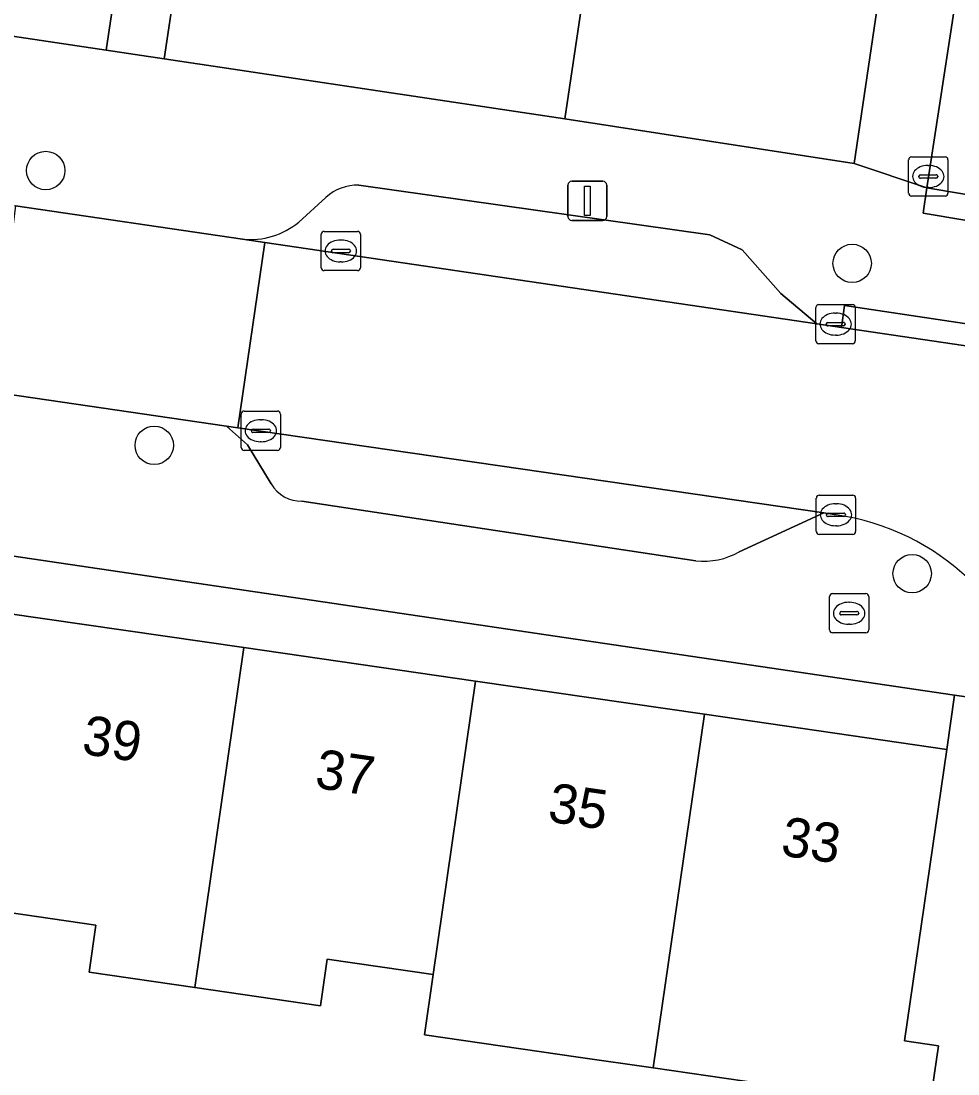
# Model space of a CAD drawing. Extents: x 163683 to 164494, y 382709 to 383872.
# Drawn here: x 164016.58 to 164040.44, y 383034.95 to 383061.77 of the extents above; entities that cross this region are included whole.
import ezdxf

# ---------------------------------------------------------------- set-up
doc = ezdxf.new("R2010")
doc.units = 0
for name, color, linetype in [('IMGEO_Boom', 7, 'Continuous'), ('IMGEO_Brandkraan', 7, 'Continuous'), ('IMGEO_Erf', 7, 'Continuous'), ('IMGEO_Kolk', 7, 'Continuous'), ('IMGEO_Lichtmast', 7, 'Continuous'), ('IMGEO_Pand', 7, 'Continuous'), ('IMGEO_Pand_nummerreeks', 7, 'Continuous'), ('IMGEO_Parkeervlak_open', 7, 'Continuous'), ('IMGEO_Rijbaan_lokaal_open', 7, 'Continuous'), ('IMGEO_Voetpad_open', 7, 'Continuous')]:
    doc.layers.add(name, color=color, linetype=linetype)

msp = doc.modelspace()

# ---------------------------------------------------------------- linework, layer by layer
at = {"layer": 'IMGEO_Boom'}
for centre in [(164017.204, 383057.959), (164037.749, 383055.594), (164019.968, 383050.961), (164039.278, 383047.694)]:
    msp.add_circle(centre, 0.489, dxfattribs=at)
at = {"layer": 'IMGEO_Brandkraan'}
for p, q in [((164037.172, 383046.259), (164037.172, 383047.111)), ((164037.247, 383047.185), (164038.099, 383047.185)), ((164038.173, 383047.111), (164038.173, 383046.259)), ((164037.474, 383046.728), (164037.872, 383046.728)), ((164037.66, 383046.965), (164037.685, 383046.965)), ((164037.431, 383046.679), (164037.431, 383046.691)), ((164037.869, 383046.642), (164037.471, 383046.642)), ((164037.915, 383046.691), (164037.915, 383046.679)), ((164037.683, 383046.405), (164037.658, 383046.405)), ((164038.099, 383046.185), (164037.247, 383046.185))]:
    msp.add_line(p, q, dxfattribs=at)
for points in [[(164037.172, 383046.259), (164037.172, 383047.111)], [(164037.247, 383047.185), (164038.099, 383047.185)], [(164038.173, 383047.111), (164038.173, 383046.259)], [(164038.099, 383046.185), (164037.247, 383046.185)]]:
    msp.add_lwpolyline(points, dxfattribs=at)
for centre, radius, start, end in [((164037.249, 383047.109), 0.0765, 91.552, 178.448), ((164037.249, 383047.109), 0.0765, 91.552, 178.448), ((164038.097, 383047.109), 0.0765, 1.552, 88.448), ((164038.097, 383047.109), 0.0765, 1.552, 88.448), ((164037.471, 383046.688), 0.0403, 85.8775, 175.7526), ((164037.876, 383046.69), 0.0386, 1.7309, 96.639), ((164037.468, 383046.678), 0.0366, 178.938, 274.7102), ((164037.872, 383046.685), 0.043, 264.8664, 352.4533), ((164037.249, 383046.261), 0.0765, 181.552, 268.448), ((164037.249, 383046.261), 0.0765, 181.552, 268.448), ((164038.097, 383046.261), 0.0765, 271.552, 358.448), ((164038.097, 383046.261), 0.0765, 271.552, 358.448)]:
    msp.add_arc(centre, radius, start, end, dxfattribs=at)
for centre, major_axis, ratio, start_param, end_param in [((164037.659, 383046.685), (-0.387, 0.002), 0.722429, 4.712389, 7.853982), ((164037.684, 383046.685), (-0.39, 0.002), 0.717154, 1.570796, 4.712389)]:
    msp.add_ellipse(centre, major_axis=major_axis, ratio=ratio, start_param=start_param, end_param=end_param, dxfattribs=at)
at = {"layer": 'IMGEO_Erf'}
for points in [[(164022.964, 383089.182), (164012.951, 383090.682), (164012.41, 383087.025), (164018.347, 383086.148), (164017.834, 383082.676), (164017.616, 383081.202), (164017.328, 383079.253), (164011.392, 383080.13), (164010.87, 383076.601), (164010.353, 383073.107), (164016.29, 383072.23), (164016.005, 383070.301), (164015.775, 383068.743), (164015.274, 383065.354), (164009.338, 383066.231), (164008.789, 383062.521), (164018.747, 383061.027)], [(164033.045, 383076.853), (164027.111, 383077.737), (164027.209, 383078.398), (164027.643, 383081.312), (164024.777, 383081.738), (164025.045, 383083.549), (164027.913, 383083.122), (164028.136, 383084.621), (164034.07, 383083.737), (164034.621, 383087.436), (164024.449, 383088.96), (164020.223, 383060.805), (164030.426, 383059.273), (164030.971, 383062.937), (164025.038, 383063.821), (164025.558, 383067.31), (164025.775, 383068.767), (164026.062, 383070.695), (164031.996, 383069.811), (164032.527, 383073.373)], [(163992.865, 383051.505), (163992.635, 383050.168), (163998.612, 383049.251), (164000, 383049.038), (164004.619, 383048.366), (164010.494, 383047.515), (164016.184, 383046.691), (164022.254, 383045.812), (164028.157, 383044.958), (164033.985, 383044.114), (164040.159, 383043.219), (164040.359, 383044.602), (164000.002, 383050.556), (163995.18, 383051.197)]]:
    msp.add_lwpolyline(points, close=True, dxfattribs=at)
msp.add_lwpolyline([(164035.482, 383034.702), (164032.681, 383035.108), (164030.771, 383035.384), (164026.853, 383035.951), (164027.075, 383037.486), (164024.374, 383037.877), (164024.202, 383036.692), (164021.001, 383037.156), (164018.311, 383037.546), (164018.484, 383038.741), (164015.104, 383039.231)], dxfattribs=at)
at = {"layer": 'IMGEO_Kolk'}
for p, q in [((164039.263, 383058.308), (164040.115, 383058.308)), ((164039.188, 383057.382), (164039.188, 383058.234)), ((164039.676, 383058.088), (164039.701, 383058.088)), ((164040.189, 383058.234), (164040.189, 383057.382)), ((164039.447, 383057.802), (164039.447, 383057.814)), ((164039.885, 383057.765), (164039.487, 383057.765)), ((164039.49, 383057.851), (164039.888, 383057.851)), ((164039.931, 383057.814), (164039.931, 383057.802)), ((164039.699, 383057.528), (164039.674, 383057.528)), ((164040.115, 383057.308), (164039.263, 383057.308)), ((164024.297, 383056.41), (164025.149, 383056.41)), ((164024.222, 383055.484), (164024.222, 383056.336)), ((164024.71, 383056.19), (164024.735, 383056.19)), ((164025.223, 383056.336), (164025.223, 383055.484)), ((164024.481, 383055.904), (164024.481, 383055.916)), ((164024.919, 383055.867), (164024.521, 383055.867)), ((164024.524, 383055.953), (164024.922, 383055.953)), ((164024.965, 383055.916), (164024.965, 383055.904)), ((164024.733, 383055.63), (164024.708, 383055.63)), ((164025.149, 383055.41), (164024.297, 383055.41)), ((164036.902, 383054.548), (164037.754, 383054.548)), ((164036.827, 383053.622), (164036.827, 383054.474)), ((164037.315, 383054.328), (164037.34, 383054.328)), ((164037.828, 383054.474), (164037.828, 383053.622)), ((164037.086, 383054.042), (164037.086, 383054.054)), ((164037.524, 383054.005), (164037.126, 383054.005)), ((164037.129, 383054.091), (164037.527, 383054.091)), ((164037.57, 383054.054), (164037.57, 383054.042)), ((164037.338, 383053.768), (164037.313, 383053.768)), ((164037.754, 383053.548), (164036.902, 383053.548)), ((164022.26, 383051.833), (164023.112, 383051.833)), ((164022.185, 383050.907), (164022.185, 383051.759)), ((164022.673, 383051.613), (164022.698, 383051.613)), ((164023.186, 383051.759), (164023.186, 383050.907)), ((164022.444, 383051.327), (164022.444, 383051.339)), ((164022.882, 383051.29), (164022.484, 383051.29)), ((164022.487, 383051.376), (164022.885, 383051.376)), ((164022.928, 383051.339), (164022.928, 383051.327)), ((164022.696, 383051.053), (164022.671, 383051.053)), ((164023.112, 383050.833), (164022.26, 383050.833)), ((164036.911, 383049.693), (164037.763, 383049.693)), ((164036.836, 383048.767), (164036.836, 383049.619)), ((164037.324, 383049.473), (164037.349, 383049.473)), ((164037.837, 383049.619), (164037.837, 383048.767)), ((164037.095, 383049.187), (164037.095, 383049.199)), ((164037.533, 383049.15), (164037.135, 383049.15)), ((164037.138, 383049.236), (164037.536, 383049.236)), ((164037.579, 383049.199), (164037.579, 383049.187)), ((164037.347, 383048.913), (164037.322, 383048.913)), ((164037.763, 383048.693), (164036.911, 383048.693))]:
    msp.add_line(p, q, dxfattribs=at)
for points in [[(164039.263, 383058.308), (164040.115, 383058.308)], [(164039.188, 383057.382), (164039.188, 383058.234)], [(164040.189, 383058.234), (164040.189, 383057.382)], [(164040.115, 383057.308), (164039.263, 383057.308)], [(164024.297, 383056.41), (164025.149, 383056.41)], [(164024.222, 383055.484), (164024.222, 383056.336)], [(164025.223, 383056.336), (164025.223, 383055.484)], [(164025.149, 383055.41), (164024.297, 383055.41)], [(164036.902, 383054.548), (164037.754, 383054.548)], [(164036.827, 383053.622), (164036.827, 383054.474)], [(164037.828, 383054.474), (164037.828, 383053.622)], [(164037.754, 383053.548), (164036.902, 383053.548)], [(164022.26, 383051.833), (164023.112, 383051.833)], [(164022.185, 383050.907), (164022.185, 383051.759)], [(164023.186, 383051.759), (164023.186, 383050.907)], [(164023.112, 383050.833), (164022.26, 383050.833)], [(164036.911, 383049.693), (164037.763, 383049.693)], [(164036.836, 383048.767), (164036.836, 383049.619)], [(164037.837, 383049.619), (164037.837, 383048.767)], [(164037.763, 383048.693), (164036.911, 383048.693)]]:
    msp.add_lwpolyline(points, dxfattribs=at)
for centre, radius, start, end in [((164039.265, 383058.232), 0.0765, 91.552, 178.448), ((164039.265, 383058.232), 0.0765, 91.552, 178.448), ((164040.113, 383058.232), 0.0765, 1.552, 88.448), ((164040.113, 383058.232), 0.0765, 1.552, 88.448), ((164039.487, 383057.811), 0.0403, 85.8775, 175.7526), ((164039.484, 383057.801), 0.0366, 178.938, 274.7102), ((164039.888, 383057.808), 0.043, 264.8664, 352.4533), ((164039.892, 383057.813), 0.0386, 1.7309, 96.639), ((164039.265, 383057.384), 0.0765, 181.552, 268.448), ((164039.265, 383057.384), 0.0765, 181.552, 268.448), ((164040.113, 383057.384), 0.0765, 271.552, 358.448), ((164040.113, 383057.384), 0.0765, 271.552, 358.448), ((164024.299, 383056.334), 0.0765, 91.552, 178.448), ((164024.299, 383056.334), 0.0765, 91.552, 178.448), ((164025.147, 383056.334), 0.0765, 1.552, 88.448), ((164025.147, 383056.334), 0.0765, 1.552, 88.448), ((164024.521, 383055.913), 0.0403, 85.8775, 175.7526), ((164024.518, 383055.903), 0.0366, 178.938, 274.7102), ((164024.922, 383055.91), 0.043, 264.8664, 352.4533), ((164024.926, 383055.915), 0.0386, 1.7309, 96.639), ((164024.299, 383055.486), 0.0765, 181.552, 268.448), ((164024.299, 383055.486), 0.0765, 181.552, 268.448), ((164025.147, 383055.486), 0.0765, 271.552, 358.448), ((164025.147, 383055.486), 0.0765, 271.552, 358.448), ((164036.904, 383054.472), 0.0765, 91.552, 178.448), ((164036.904, 383054.472), 0.0765, 91.552, 178.448), ((164037.752, 383054.472), 0.0765, 1.552, 88.448), ((164037.752, 383054.472), 0.0765, 1.552, 88.448), ((164037.126, 383054.051), 0.0403, 85.8775, 175.7526), ((164037.123, 383054.041), 0.0366, 178.938, 274.7102), ((164037.527, 383054.048), 0.043, 264.8664, 352.4533), ((164037.531, 383054.053), 0.0386, 1.7309, 96.639), ((164036.904, 383053.624), 0.0765, 181.552, 268.448), ((164036.904, 383053.624), 0.0765, 181.552, 268.448), ((164037.752, 383053.624), 0.0765, 271.552, 358.448), ((164037.752, 383053.624), 0.0765, 271.552, 358.448), ((164022.262, 383051.757), 0.0765, 91.552, 178.448), ((164022.262, 383051.757), 0.0765, 91.552, 178.448), ((164023.11, 383051.757), 0.0765, 1.552, 88.448), ((164023.11, 383051.757), 0.0765, 1.552, 88.448), ((164022.484, 383051.336), 0.0403, 85.8775, 175.7526), ((164022.481, 383051.326), 0.0366, 178.938, 274.7102), ((164022.885, 383051.333), 0.043, 264.8664, 352.4533), ((164022.889, 383051.338), 0.0386, 1.7309, 96.639), ((164022.262, 383050.909), 0.0765, 181.552, 268.448), ((164022.262, 383050.909), 0.0765, 181.552, 268.448), ((164023.11, 383050.909), 0.0765, 271.552, 358.448), ((164023.11, 383050.909), 0.0765, 271.552, 358.448), ((164036.913, 383049.617), 0.0765, 91.552, 178.448), ((164036.913, 383049.617), 0.0765, 91.552, 178.448), ((164037.761, 383049.617), 0.0765, 1.552, 88.448), ((164037.761, 383049.617), 0.0765, 1.552, 88.448), ((164037.135, 383049.196), 0.0403, 85.8775, 175.7526), ((164037.132, 383049.186), 0.0366, 178.938, 274.7102), ((164037.536, 383049.193), 0.043, 264.8664, 352.4533), ((164037.54, 383049.198), 0.0386, 1.7309, 96.639), ((164036.913, 383048.769), 0.0765, 181.552, 268.448), ((164036.913, 383048.769), 0.0765, 181.552, 268.448), ((164037.761, 383048.769), 0.0765, 271.552, 358.448), ((164037.761, 383048.769), 0.0765, 271.552, 358.448)]:
    msp.add_arc(centre, radius, start, end, dxfattribs=at)
for centre, major_axis, ratio, start_param, end_param in [((164039.675, 383057.808), (-0.387, 0.002), 0.722429, 4.712389, 7.853982), ((164039.7, 383057.808), (-0.39, 0.002), 0.717154, 1.570796, 4.712389), ((164024.709, 383055.91), (-0.387, 0.002), 0.722429, 4.712389, 7.853982), ((164024.734, 383055.91), (-0.39, 0.002), 0.717154, 1.570796, 4.712389), ((164037.314, 383054.048), (-0.387, 0.002), 0.722429, 4.712389, 7.853982), ((164037.339, 383054.048), (-0.39, 0.002), 0.717154, 1.570796, 4.712389), ((164022.672, 383051.333), (-0.387, 0.002), 0.722429, 4.712389, 7.853982), ((164022.697, 383051.333), (-0.39, 0.002), 0.717154, 1.570796, 4.712389), ((164037.323, 383049.193), (-0.387, 0.002), 0.722429, 4.712389, 7.853982), ((164037.348, 383049.193), (-0.39, 0.002), 0.717154, 1.570796, 4.712389)]:
    msp.add_ellipse(centre, major_axis=major_axis, ratio=ratio, start_param=start_param, end_param=end_param, dxfattribs=at)
at = {"layer": 'IMGEO_Lichtmast'}
for p, q in [((164030.508, 383056.787), (164030.508, 383057.587)), ((164030.508, 383057.587), (164030.508, 383056.787)), ((164030.608, 383057.687), (164031.398, 383057.687)), ((164031.398, 383057.687), (164030.608, 383057.687)), ((164031.498, 383057.587), (164031.498, 383056.787)), ((164031.498, 383056.787), (164031.498, 383057.587)), ((164031.398, 383056.687), (164030.608, 383056.687)), ((164030.608, 383056.687), (164031.398, 383056.687))]:
    msp.add_line(p, q, dxfattribs=at)
msp.add_lwpolyline([(164030.928, 383057.562), (164031.078, 383057.562), (164031.078, 383056.812), (164030.928, 383056.812), (164030.928, 383057.562)], dxfattribs=at)
for centre, start, end in [((164030.608, 383057.587), 90, 180), ((164030.608, 383057.587), 90, 180), ((164031.398, 383057.587), 0, 90), ((164031.398, 383057.587), 360, 90), ((164030.608, 383056.787), 180, 270), ((164030.608, 383056.787), 180, 270), ((164031.398, 383056.787), 270, 0), ((164031.398, 383056.787), 270, 0)]:
    msp.add_arc(centre, 0.1, start, end, dxfattribs=at)
at = {"layer": 'IMGEO_Pand'}
for points in [[(164025.558, 383067.31), (164025.038, 383063.821), (164030.971, 383062.937), (164030.426, 383059.273), (164037.802, 383058.142), (164038.851, 383065.265)], [(164016.184, 383046.691), (164015.104, 383039.231), (164018.484, 383038.741), (164018.311, 383037.546), (164021.001, 383037.156), (164022.254, 383045.812)], [(164028.157, 383044.958), (164022.254, 383045.812), (164021.001, 383037.156), (164024.202, 383036.692), (164024.374, 383037.877), (164027.075, 383037.486)], [(164028.157, 383044.958), (164027.075, 383037.486), (164026.853, 383035.951), (164030.771, 383035.384), (164032.681, 383035.108), (164033.985, 383044.114)], [(164033.985, 383044.114), (164032.681, 383035.108), (164035.482, 383034.702), (164035.417, 383034.26), (164039.652, 383033.645), (164039.946, 383035.673), (164039.085, 383035.797), (164040.159, 383043.219)]]:
    msp.add_lwpolyline(points, close=True, dxfattribs=at)
at = {"layer": 'IMGEO_Parkeervlak_open'}
for points in [[(164034.127, 383056.318), (164025.178, 383057.585)], [(164024.342, 383057.275), (164023.656, 383056.646)], [(164022.215, 383056.211), (164022.788, 383056.127), (164036.851, 383054.058), (164035.934, 383054.824), (164034.947, 383055.94), (164034.127, 383056.318)], [(164034.871, 383048.252), (164037.025, 383049.239), (164022.095, 383051.409), (164021.809, 383051.451), (164022.349, 383050.977), (164022.951, 383049.98)], [(164023.732, 383049.542), (164033.767, 383048.021)]]:
    msp.add_lwpolyline(points, dxfattribs=at)
for centre, radius, start, end in [((164025.134, 383056.421), 1.165, 87.8374, 132.8535), ((164022.405, 383058.186), 1.984, 264.5086, 309.0867), ((164023.7, 383050.4), 0.858, 209.2735, 272.1574), ((164033.968, 383049.812), 1.802, 263.5815, 300.0546)]:
    msp.add_arc(centre, radius, start, end, dxfattribs=at)
at = {"layer": 'IMGEO_Rijbaan_lokaal_open'}
for points in [[(164043.851, 383085.289), (164043.854, 383085.06), (164043.271, 383081.092), (164039.653, 383057.519), (164042.978, 383056.96), (164045.921, 383076.806), (164045.976, 383077.163), (164046.054, 383077.691)], [(164053.938, 383046.726), (164055.214, 383046.537), (164072.333, 383043.999), (164073.069, 383048.725), (164056.229, 383051.203), (164055.32, 383051.337), (164048.406, 383052.355), (164044.209, 383052.972), (164037.476, 383053.965), (164036.851, 383054.058), (164022.788, 383056.127), (164022.095, 383051.409), (164037.025, 383049.239), (164037.34, 383049.193)]]:
    msp.add_lwpolyline(points, dxfattribs=at)
for points in [[(164042.84, 383056.324), (164042.911, 383056.507), (164042.978, 383056.96), (164039.653, 383057.519), (164039.556, 383056.876)], [(164022.095, 383051.409), (164022.788, 383056.127), (164022.215, 383056.211), (164016.437, 383057.059), (164015.819, 383052.322), (164021.809, 383051.451)]]:
    msp.add_lwpolyline(points, close=True, dxfattribs=at)
msp.add_arc((164036.439, 383043.016), 6.242, 11.7018, 81.7045, dxfattribs=at)
at = {"layer": 'IMGEO_Voetpad_open'}
for points in [[(164024.449, 383088.96), (164022.964, 383089.182), (164018.747, 383061.027), (164020.223, 383060.805)], [(164043.271, 383081.092), (164043.854, 383085.06), (164043.851, 383085.289), (164043.843, 383085.984), (164041.955, 383086.344), (164040.913, 383079.27), (164039.878, 383072.242), (164038.851, 383065.265), (164037.802, 383058.142), (164039.653, 383057.519)], [(164044.209, 383052.972), (164044.29, 383053.516), (164037.557, 383054.519), (164037.476, 383053.965)]]:
    msp.add_lwpolyline(points, close=True, dxfattribs=at)
for points in [[(164056.633, 383055.356), (164054.596, 383055.242), (164054.5, 383054.599), (164051.188, 383055.135), (164042.84, 383056.324), (164039.556, 383056.876), (164039.653, 383057.519), (164037.802, 383058.142), (164030.426, 383059.273), (164020.223, 383060.805), (164018.747, 383061.027), (164008.789, 383062.521), (164001.464, 383063.621), (163999.41, 383063.224), (163999.316, 383062.59), (163995.848, 383063.119), (163990.75, 383063.896), (163988.526, 383062.149), (163985.466, 383059.738)], [(164004.603, 383060.549), (164014.034, 383059.188), (164015.06, 383058.752), (164016.315, 383057.077), (164016.437, 383057.059), (164022.215, 383056.211)], [(164025.178, 383057.585), (164034.127, 383056.318), (164034.947, 383055.94), (164035.934, 383054.824), (164036.851, 383054.058), (164037.476, 383053.965), (164037.557, 383054.519), (164044.29, 383053.516), (164044.209, 383052.972), (164048.406, 383052.355), (164048.485, 383052.884), (164055.396, 383051.842), (164055.32, 383051.337), (164056.229, 383051.203), (164057.386, 383051.395), (164058.376, 383052.117)], [(164023.656, 383056.646), (164024.342, 383057.275)], [(164022.951, 383049.98), (164022.349, 383050.977), (164021.809, 383051.451), (164015.819, 383052.322)], [(163990.275, 383051.849), (163992.865, 383051.505), (163995.18, 383051.197), (164000.002, 383050.556), (164040.359, 383044.602), (164042.552, 383044.282)], [(164033.767, 383048.021), (164023.732, 383049.542)], [(164037.34, 383049.193), (164037.025, 383049.239), (164034.871, 383048.252)], [(164042.552, 383044.282), (164040.359, 383044.602), (164040.159, 383043.219), (164039.085, 383035.797), (164039.946, 383035.673), (164039.652, 383033.645), (164038.176, 383023.49), (164037.66, 383019.957), (164036.238, 383020.151), (164035.986, 383018.399), (164033.287, 383000), (164030.709, 382982.425), (164030.284, 382979.529), (164025.036, 382943.754), (164024.242, 382938.326), (164023.876, 382935.821), (164023.007, 382929.886), (164026.085, 382929.437), (164026.287, 382930.934), (164026.311, 382931.123), (164026.328, 382931.232)]]:
    msp.add_lwpolyline(points, dxfattribs=at)
for centre, radius, start, end in [((164025.134, 383056.421), 1.165, 87.8374, 132.8535), ((164022.405, 383058.186), 1.984, 264.5086, 309.0867), ((164023.7, 383050.4), 0.858, 209.2735, 272.1574), ((164036.439, 383043.016), 6.242, 11.7018, 81.7045), ((164033.968, 383049.812), 1.802, 263.5815, 300.0546)]:
    msp.add_arc(centre, radius, start, end, dxfattribs=at)

# ---------------------------------------------------------------- texts
at = {"layer": 'IMGEO_Pand_nummerreeks'}
for s, p in [('39', (164018.097, 383043.108)), ('37', (164024.032, 383042.246)), ('35', (164029.967, 383041.385)), ('33', (164035.903, 383040.523))]:
    msp.add_text(s, height=1, rotation=351.7393, dxfattribs=at).set_placement(p)

doc.saveas('drawing.dxf')
